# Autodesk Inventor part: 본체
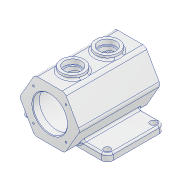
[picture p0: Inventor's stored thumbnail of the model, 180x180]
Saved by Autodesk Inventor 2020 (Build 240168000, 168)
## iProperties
Created: 2021-06
Part Number: 본체
Material: 알루미늄 6061
Document SubType Name: Modeling
Designer: Administrator
Density: 2.7 g/cm^3
Appearance: 알루미늄 - 평지
Mass: 1495.15 g
Surface Area: 1102.35 cm^2
Volume: 553.759 cm^3
Author: Administrator
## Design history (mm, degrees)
sketch "스케치1" dims "d0" = 105
  geometry: L1 (26.25, 45.466)-(52.5, 0); L2 (52.5, 0)-(26.25, -45.466); L3 (26.25, -45.466)-(-26.25, -45.466); L4 (-26.25, -45.466)-(-52.5, 0); L5 (-52.5, 0)-(-26.25, 45.466); L6 (-26.25, 45.466)-(26.25, 45.466); 3 further points
  constraints: 12 end point, 2 coincident, 1 horizontal, 16 other
extrude "돌출1" new body sketch "스케치1" stored distance "d1" = 140; taper "d2" = 0 deg
fillet "모깎기3" dims "d63" = 8
node "작업 평면1"
sketch "스케치2"
  geometry: L1 (75, -55)-(-75, -55); L2 (-75, -55)-(-75, 45); L3 (-75, 45)-(75, 45); L4 (75, 45)-(75, -55); L5 (28.559, 70)-(50.191, 70) reference; 3 further points
  constraints: 8 end point, 2 parallel, 1 horizontal, 1 perpendicular
  dimensions: "d4" = 25 distance between parallel lines of L3 L5; "d5" = 100 distance between parallel lines of L1 L3; "d6" = 150 distance between parallel lines of L2 L4; "d7" = 75 distance from line of point (0, 0) L4
extrude "돌출2" join sketch "스케치2" distance "d8" = 12; taper "d9" = 0 deg
node "작업 평면2"
sketch "스케치3"
  geometry: L1 (-21.631, 70)-(21.631, 70) reference; C1 r 20 at (0, 30); C2 r 20 at (0, -30); 3 further points
  constraints: 2 centre point, 2 vertical alignment, 1 equal radius
  dimensions: "d11" = 40 diameter of C1; "d12" = 40 distance from line of L1 C1.centre; "d13" = 60 distance of C2.centre C1.centre
extrude "돌출3" join sketch "스케치3" stored distance "d14" = 12; taper "d15" = 0 deg
sketch "스케치5"
  geometry: L1 (0, 58)-(0, -58); L2 (0, -58)-(37.5, -58); L3 (37.5, -58)-(37.5, 58); L4 (37.5, 58)-(0, 58); L5 (45.466, 70)-(0, 70) reference; L6 (0, -70)-(45.466, -70) reference; 1 further point
  constraints: 8 end point, 3 perpendicular, 1 vertical, 1 vertical alignment
  dimensions: "d21" = 12 distance between parallel lines of L5 L4; "d22" = 12 distance between parallel lines of L6 L2; "d23" = 75 diameter of L3 L1
revolve "회전1" sketch "스케치5" stored, may be unused: angle "d24" = 90 deg
sketch "스케치6"
  geometry: C1 r 30 at (0, 0); 1 further point
  constraints: 1 centre point, 1 coincident
  dimensions: "d25" = 60 diameter of C1
extrude "돌출4" cut sketch "스케치6" distance "d26" = 12; taper "d27" = 0 deg
sketch "스케치7"
  geometry: C1 r 30 at (0, 0); 2 further points
  constraints: 1 centre point, 1 coincident
  dimensions: "d28" = 60 diameter of C1
extrude "돌출5" cut sketch "스케치7" distance "d29" = 12; taper "d30" = 0 deg
sketch "스케치8"
  geometry: C1 r 20 at (0, 0) reference; C2 r 20 at (0, 60) reference; 3 further points
  constraints: 2 coincident
hole "구멍1" sketch "스케치8" at (0, 0), (0, 60) diameter "d31" = 25; stored, may be unused: countersink angle "d35" = 90 deg, drill point angle "d37" = 0 deg; dims "d32" = 6, "d33" = 30, "d34" = 8, "d36" = 20
sketch "스케치9"
  geometry: L1 (0, 0)-(0, 40); L2 (0, 0)-(-28.284, 28.284); A1 r 40 centre (0, 0) between (0, 40) and (-28.284, 28.284); 2 further points
  constraints: 4 end point, 2 coincident, 2 point on circle, 1 centre point, 1 vertical
  dimensions: "d38" = 80 diameter of A1; "d39" = 45 deg angle of L1 L2
hole "구멍2" sketch "스케치9" at (-28.284, 28.284) diameter "d40" = 3.242; stored, may be unused: countersink angle "d44" = 90 deg, drill point angle "d46" = 120 deg; dims "d41" = 8, "d42" = 30, "d43" = 8, "d45" = 10
sketch "스케치12"
  geometry: 2 further points
  constraints: 1 vertical alignment
  dimensions: "d74" = 40 distance of point (0, 0) point (0, 40)
hole "구멍4" sketch "스케치12" at (0, 40) diameter "d75" = 3.242; stored, may be unused: countersink angle "d79" = 90 deg, drill point angle "d81" = 120 deg; dims "d76" = 8, "d77" = 30, "d78" = 8, "d80" = 10
sketch "스케치10"
  geometry: L1 (-75, -45)-(75, -45) reference; L2 (-75, 55)-(-75, -45) reference; L3 (75, -45)-(75, 55) reference; L4 (75, 55)-(-75, 55) reference; 5 further points
  constraints: 2 horizontal alignment, 2 vertical alignment
  dimensions: "d50" = 10 distance from line of point (-65, -35) L1; "d51" = 10 distance from line of L2 point (-65, -35); "d52" = 10 distance from line of L3 point (65, -35); "d53" = 10 distance from line of L4 point (65, 45)
hole "구멍3" sketch "스케치10" at (-65, -35), (-65, 45), (65, 45), (65, -35) diameter "d54" = 11; stored, may be unused: countersink angle "d58" = 90 deg, drill point angle "d60" = 120 deg; dims "d55" = 8, "d56" = 30, "d57" = 8, "d59" = 10
fillet "모깎기1" dims "d61" = 10
fillet "모깎기4" dims "d64" = 5
fillet "모깎기5" dims "d65" = 3
fillet "모깎기6" dims "d66" = 3
chamfer "모따기1" distance "d67" = 1; stored, may be unused: second distance "d68" = 2, angle "d69" = 45 deg
sketch "스케치11"
  geometry: L1 (-75, 45)-(-75, -35) reference; L2 (-65, -45)-(-32.293, -45) reference; 2 further points
  constraints: 1 other
  dimensions: "d71" = 14 distance from line of L1 point (-61, 5); "d85" = 50 distance from line of L2 point (-61, 5)
feature "엠보싱1" sketch "스케치11" dims "d72" = 0.5, "d73" = 0
node "솔리드1"
pattern_circular "원형 패턴1" dims angle "d48" = 360 deg
pattern_circular "원형 패턴2" dims angle "d83" = 360 deg
feature "A9D066F2-1C7D-4E18-AEED-F7BC21143FA4" dims "d54" = 11, "d55" = 8, "d56" = 30, "d57" = 8, "d58" = 90 deg, "d59" = 10, "d60" = 120 deg
other parameters: "d10" = 52.5
